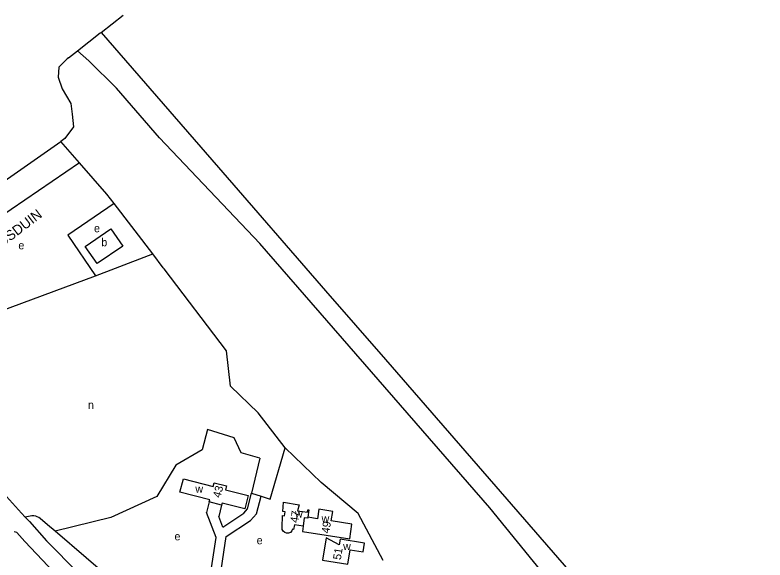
# Model space of a CAD drawing. Extents: x 155696 to 157795, y 382328 to 384028.
# Drawn here: x 157284.9 to 157659.9, y 383615.4 to 383887.8 of the extents above; entities that cross this region are included whole.
import ezdxf

# ---------------------------------------------------------------- set-up
doc = ezdxf.new("R2010")
doc.units = 0
for name, color, linetype in [('BLT_Basislijn', 7, 'Continuous'), ('BLT_Bebouwing', 7, 'Continuous'), ('BLT_Centroide', 7, 'Continuous'), ('BLT_Huisnummer', 7, 'Continuous'), ('BLT_Onderverdeling_panden', 7, 'Continuous'), ('BLT_Straatnaam', 7, 'Continuous')]:
    doc.layers.add(name, color=color, linetype=linetype)

msp = doc.modelspace()

# ---------------------------------------------------------------- linework, layer by layer
at = {"layer": 'BLT_Basislijn'}
for p, q in [((157327.95, 383879.08), (157338.98, 383887.78)), ((157316.1, 383869.83), (157327.59, 383878.8)), ((157327.59, 383878.8), (157327.95, 383879.08)), ((157327.95, 383879.08), (157386.66, 383811.57)), ((157311.7, 383866.39), (157316.1, 383869.83)), ((157256.07, 383788.51), (157307.92, 383824.64)), ((157317.19, 383813.98), (157307.92, 383824.64)), ((157317.19, 383813.98), (157214.3, 383743.57)), ((157470.18, 383715.55), (157578.96, 383590.55)), ((157412.55, 383645.83), (157420.02, 383671.4)), ((157407.32, 383666.22), (157403.26, 383648.87)), ((157403.26, 383648.87), (157408.02, 383647.31)), ((157382.09, 383644.49), (157380.66, 383639.17)), ((157408.02, 383647.31), (157412.55, 383645.83)), ((157388.24, 383642.89), (157386.79, 383637.14))]:
    msp.add_line(p, q, dxfattribs=at)
for points in [[(157656.52, 383478.02), (157659.92, 383481.07), (157633.13, 383510.96), (157585.63, 383563.31), (157573.14, 383580.85), (157557.95, 383597.6), (157522.42, 383641.47), (157407.36, 383773.66), (157357.26, 383826.39), (157335.74, 383851.25), (157321.8, 383864.89), (157316.1, 383869.83)], [(157311.7, 383866.39), (157310.95, 383865.8), (157306.93, 383861.78), (157306.47, 383856.7), (157308.58, 383850.89), (157312.89, 383843.5), (157313.55, 383838.23), (157314.26, 383831.86), (157309.85, 383825.99), (157307.92, 383824.64)], [(157334.46, 383793.59), (157330.9, 383798.23), (157317.19, 383813.98)], [(157386.66, 383811.57), (157440.23, 383749.98), (157470.18, 383715.55)], [(157334.46, 383793.59), (157311.28, 383777.71), (157325.16, 383757.5)], [(157353.77, 383768.41), (157334.46, 383793.59)], [(157325.16, 383757.5), (157335.2, 383761.23), (157353.77, 383768.41)], [(157359.44, 383760.94), (157359.03, 383761.47), (157353.77, 383768.41)], [(157392.73, 383702.32), (157390.7, 383719.93), (157359.44, 383760.94)], [(157227.49, 383721.31), (157241.04, 383726.3), (157325.16, 383757.5)], [(157420.02, 383671.4), (157406.45, 383689.02), (157392.73, 383702.32)], [(157290.02, 383636.87), (157288.12, 383638.83), (157277.72, 383650.43), (157264.59, 383666.09), (157259.09, 383673.04), (157250.71, 383684.99), (157242.84, 383697.16)], [(157407.32, 383666.22), (157398.07, 383669.05), (157394.48, 383676.44), (157381.21, 383680.69), (157378.58, 383670.52), (157365.36, 383662.87), (157355.81, 383647.07), (157332.85, 383636.61), (157305.03, 383629.74)], [(157469.07, 383615.2), (157456.44, 383638.57), (157438.07, 383654.12), (157420.02, 383671.4)], [(157388.79, 383631.9), (157399.36, 383638.88), (157401.18, 383640.95), (157403.26, 383648.87)], [(157390.55, 383627.07), (157402.68, 383635.07), (157405.72, 383638.54), (157408.02, 383647.31)], [(157305.03, 383629.74), (157301.26, 383632.99), (157297.59, 383636.11), (157296.84, 383636.64), (157296.09, 383637.01), (157295.31, 383637.26), (157294.38, 383637.4), (157293.38, 383637.4), (157290.02, 383636.87)], [(157382.56, 383607.19), (157385.43, 383626.67), (157380.66, 383639.17)], [(157388.79, 383631.9), (157386.79, 383637.14)], [(157292.2, 383634.61), (157290.02, 383636.87)], [(157292.2, 383634.61), (157300.65, 383625), (157316.64, 383608.76), (157322.08, 383603.62), (157335.35, 383592.38)], [(157312.33, 383601.15), (157310.1, 383603.15), (157289.93, 383624.65), (157285.78, 383629.16), (157284.5, 383629.47)], [(157340.86, 383599), (157320.51, 383616.46), (157305.03, 383629.74)], [(157387.59, 383607.07), (157390.55, 383627.07)]]:
    msp.add_lwpolyline(points, dxfattribs=at)
at = {"layer": 'BLT_Bebouwing'}
for points in [[(157325.99, 383763.52), (157320.07, 383772.17), (157332.88, 383780.92), (157338.79, 383772.29)], [(157440.45, 383626.44), (157438.69, 383615.26), (157451.38, 383613.26), (157452.53, 383620.53), (157458.94, 383619.48), (157459.63, 383623.85), (157447.43, 383625.78), (157446.98, 383622.93)]]:
    msp.add_lwpolyline(points, close=True, dxfattribs=at)
for points in [[(157367.43, 383649.34), (157369.15, 383655.95), (157384.08, 383652.1), (157384.58, 383654.04), (157390.71, 383652.45), (157390.21, 383650.51), (157401.55, 383647.57)], [(157382.09, 383644.49), (157382.35, 383645.47), (157367.43, 383649.34)], [(157388.24, 383642.89), (157382.09, 383644.49)], [(157401.55, 383647.57), (157399.82, 383640.96), (157388.5, 383643.88), (157388.24, 383642.89)], [(157429.03, 383632.32), (157424.69, 383632.99), (157424.1, 383630.71), (157423.76, 383630.8), (157423.34, 383629.91), (157422.63, 383629.23), (157421.71, 383628.85), (157420.74, 383628.8), (157419.81, 383629.17), (157419.07, 383629.79), (157418.59, 383630.66), (157418.46, 383631.64), (157418.75, 383637.63), (157419.71, 383637.49), (157420.06, 383639.5), (157418.86, 383639.71), (157419.1, 383644.27)], [(157419.1, 383644.27), (157426.97, 383643.05), (157426.19, 383640.03), (157431.24, 383639.24)], [(157429.03, 383632.32), (157428.7, 383629.72), (157452.28, 383625.99), (157453.42, 383633.25), (157443.03, 383634.91), (157443.78, 383639.7), (157436.89, 383640.79), (157436.14, 383636.01), (157431.35, 383636.77)], [(157431.24, 383639.24), (157431.4, 383640.54), (157431.84, 383640.47), (157431.35, 383636.77)]]:
    msp.add_lwpolyline(points, dxfattribs=at)
at = {"layer": 'BLT_Onderverdeling_panden'}
msp.add_lwpolyline([(157431.35, 383636.77), (157431.29, 383636.28), (157429.59, 383636.51), (157429.03, 383632.32)], dxfattribs=at)

# ---------------------------------------------------------------- texts
at = {"layer": 'BLT_Centroide'}
for s, p in [('e', (157324.44, 383779.22)), ('b', (157328.1, 383772.22)), ('e', (157286.62, 383770.69)), ('n', (157321.42, 383690.94)), ('w', (157375.12, 383648.98)), ('w', (157424.95, 383636.62)), ('w', (157438.21, 383634.15)), ('e', (157364.66, 383625.25)), ('e', (157405.76, 383623.27)), ('w', (157448.98, 383620.37))]:
    msp.add_text(s, height=4, dxfattribs=at).set_placement(p)
at = {"layer": 'BLT_Huisnummer'}
for s, rotation, p in [('43', 75.0786, (157387.61, 383646.17)), ('47', 80.9916, (157426.4, 383633.77)), ('49', 80.9916, (157442.04, 383628.5)), ('51', 80.9916, (157447.83, 383615.27))]:
    msp.add_text(s, height=4, rotation=rotation, dxfattribs=at).set_placement(p)
at = {"layer": 'BLT_Straatnaam'}
msp.add_text('BOSDUIN', height=5, rotation=37.4543, dxfattribs=at).set_placement((157274.75, 383768.65))

doc.saveas('drawing.dxf')
